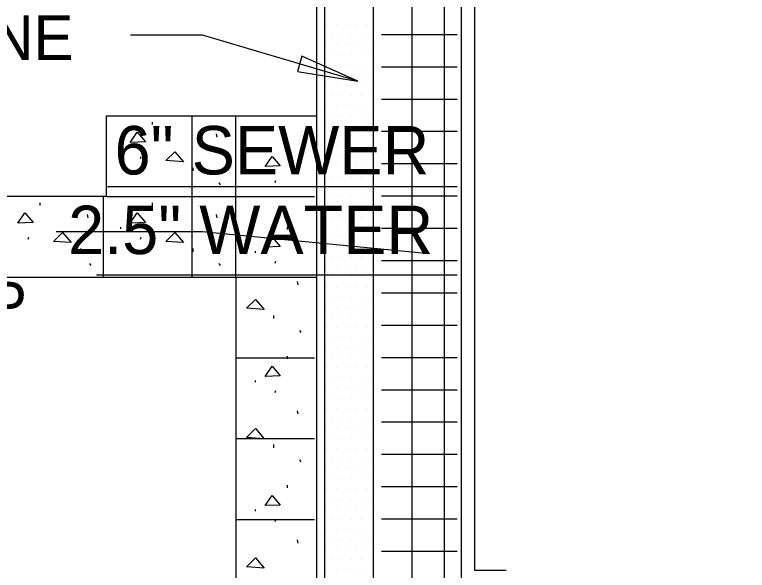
# Model space of a CAD drawing. Extents: x 6712138 to 6712574, y 1869536 to 1870160.
# Drawn here: x 6712232.49 to 6712277.85, y 1869768.11 to 1869802.53 of the extents above; entities that cross this region are included whole.
import ezdxf

# ---------------------------------------------------------------- set-up
doc = ezdxf.new("R2010")
doc.units = 0
for name, color, linetype in [('A-ANNO-TEXT', 7, 'Continuous'), ('A-FLOR-OTLN', 7, 'Continuous'), ('A-FLOR-PATT', 7, 'Continuous'), ('A-WALL-FULL-EXT', 7, 'Continuous'), ('L-SITE-PAVE', 7, 'Continuous')]:
    doc.layers.add(name, color=color, linetype=linetype)

msp = doc.modelspace()

# ---------------------------------------------------------------- linework, layer by layer
at = {"layer": 'A-ANNO-TEXT'}
for p, q in [((6712241.186, 1869801.248), (6712239.67, 1869801.248)), ((6712241.186, 1869801.248), (6712239.67, 1869801.248)), ((6712244.128, 1869801.248), (6712241.186, 1869801.248)), ((6712244.128, 1869801.248), (6712241.186, 1869801.248)), ((6712253.734, 1869798.414), (6712244.128, 1869801.248)), ((6712253.734, 1869798.414), (6712244.128, 1869801.248)), ((6712250.277, 1869799.948), (6712249.997, 1869799.001)), ((6712250.277, 1869799.948), (6712249.997, 1869799.001)), ((6712250.277, 1869799.948), (6712249.997, 1869799.001)), ((6712250.277, 1869799.948), (6712249.997, 1869799.001)), ((6712253.734, 1869798.414), (6712250.277, 1869799.948)), ((6712253.734, 1869798.414), (6712250.277, 1869799.948)), ((6712253.734, 1869798.414), (6712250.277, 1869799.948)), ((6712253.734, 1869798.414), (6712250.277, 1869799.948)), ((6712249.997, 1869799.001), (6712253.734, 1869798.414)), ((6712249.997, 1869799.001), (6712253.734, 1869798.414)), ((6712249.997, 1869799.001), (6712253.734, 1869798.414)), ((6712249.997, 1869799.001), (6712253.734, 1869798.414)), ((6712238.243, 1869791.874), (6712259.891, 1869791.874)), ((6712241.186, 1869789.085), (6712235.058, 1869789.085)), ((6712241.186, 1869789.085), (6712235.058, 1869789.085)), ((6712244.128, 1869789.085), (6712241.186, 1869789.085)), ((6712244.128, 1869789.085), (6712241.186, 1869789.085)), ((6712257.929, 1869787.742), (6712244.128, 1869789.085)), ((6712257.929, 1869787.742), (6712244.128, 1869789.085)), ((6712237.559, 1869786.417), (6712259.891, 1869786.417))]:
    msp.add_line(p, q, dxfattribs=at)
at = {"layer": 'A-FLOR-OTLN'}
for p, q in [((6712238.183, 1869791.27), (6712238.183, 1869796.27)), ((6712238.183, 1869796.27), (6712251.183, 1869796.27)), ((6712238.183, 1869791.27), (6712188.487, 1869791.27)), ((6712188.487, 1869786.27), (6712246.183, 1869786.27)), ((6712246.183, 1869786.27), (6712246.183, 1869759.106))]:
    msp.add_line(p, q, dxfattribs=at)
for points in [[(6712251.183, 1869839.781), (6712251.183, 1869722.323), (6712419.14, 1869722.323), (6712419.14, 1869718.864), (6712468.641, 1869718.864), (6712468.641, 1869839.781)], [(6712251.683, 1869839.281), (6712251.683, 1869722.823), (6712419.64, 1869722.823), (6712419.64, 1869719.364), (6712468.141, 1869719.364), (6712468.141, 1869839.281)]]:
    msp.add_lwpolyline(points, close=True, dxfattribs=at)
msp.add_lwpolyline([(6712254.683, 1869836.281), (6712254.683, 1869725.823), (6712428.12, 1869725.823)], dxfattribs=at)
at = {"layer": 'A-FLOR-PATT'}
for p, q in [((6712257.11, 1869726.344), (6712257.11, 1869835.76)), ((6712259.11, 1869763.052), (6712259.11, 1869835.76)), ((6712251.774, 1869801.907), (6712251.774, 1869801.907)), ((6712252.399, 1869801.907), (6712252.399, 1869801.907)), ((6712253.024, 1869801.907), (6712253.024, 1869801.907)), ((6712253.649, 1869801.907), (6712253.649, 1869801.907)), ((6712254.274, 1869801.907), (6712254.274, 1869801.907)), ((6712252.087, 1869801.282), (6712252.087, 1869801.282)), ((6712252.712, 1869801.282), (6712252.712, 1869801.282)), ((6712253.337, 1869801.282), (6712253.337, 1869801.282)), ((6712253.962, 1869801.282), (6712253.962, 1869801.282)), ((6712254.587, 1869801.282), (6712254.587, 1869801.282)), ((6712259.891, 1869801.281), (6712255.204, 1869801.281)), ((6712251.774, 1869800.657), (6712251.774, 1869800.657)), ((6712252.399, 1869800.657), (6712252.399, 1869800.657)), ((6712253.024, 1869800.657), (6712253.024, 1869800.657)), ((6712253.649, 1869800.657), (6712253.649, 1869800.657)), ((6712254.274, 1869800.657), (6712254.274, 1869800.657)), ((6712252.087, 1869800.032), (6712252.087, 1869800.032)), ((6712252.712, 1869800.032), (6712252.712, 1869800.032)), ((6712253.337, 1869800.032), (6712253.337, 1869800.032)), ((6712253.962, 1869800.032), (6712253.962, 1869800.032)), ((6712254.587, 1869800.032), (6712254.587, 1869800.032)), ((6712251.774, 1869799.407), (6712251.774, 1869799.407)), ((6712252.399, 1869799.407), (6712252.399, 1869799.407)), ((6712253.024, 1869799.407), (6712253.024, 1869799.407)), ((6712253.649, 1869799.407), (6712253.649, 1869799.407)), ((6712254.274, 1869799.407), (6712254.274, 1869799.407)), ((6712259.891, 1869799.281), (6712255.204, 1869799.281)), ((6712252.087, 1869798.782), (6712252.087, 1869798.782)), ((6712252.712, 1869798.782), (6712252.712, 1869798.782)), ((6712253.337, 1869798.782), (6712253.337, 1869798.782)), ((6712253.962, 1869798.782), (6712253.962, 1869798.782)), ((6712254.587, 1869798.782), (6712254.587, 1869798.782)), ((6712251.774, 1869798.157), (6712251.774, 1869798.157)), ((6712252.399, 1869798.157), (6712252.399, 1869798.157)), ((6712253.024, 1869798.157), (6712253.024, 1869798.157)), ((6712253.649, 1869798.157), (6712253.649, 1869798.157)), ((6712254.274, 1869798.157), (6712254.274, 1869798.157)), ((6712252.087, 1869797.532), (6712252.087, 1869797.532)), ((6712252.712, 1869797.532), (6712252.712, 1869797.532)), ((6712253.337, 1869797.532), (6712253.337, 1869797.532)), ((6712253.962, 1869797.532), (6712253.962, 1869797.532)), ((6712254.587, 1869797.532), (6712254.587, 1869797.532)), ((6712259.891, 1869797.281), (6712255.204, 1869797.281)), ((6712251.774, 1869796.907), (6712251.774, 1869796.907)), ((6712252.399, 1869796.907), (6712252.399, 1869796.907)), ((6712253.024, 1869796.907), (6712253.024, 1869796.907)), ((6712253.649, 1869796.907), (6712253.649, 1869796.907)), ((6712254.274, 1869796.907), (6712254.274, 1869796.907)), ((6712252.087, 1869796.282), (6712252.087, 1869796.282)), ((6712252.712, 1869796.282), (6712252.712, 1869796.282)), ((6712253.337, 1869796.282), (6712253.337, 1869796.282)), ((6712253.962, 1869796.282), (6712253.962, 1869796.282)), ((6712254.587, 1869796.282), (6712254.587, 1869796.282)), ((6712241.033, 1869795.715), (6712241.033, 1869795.875)), ((6712251.774, 1869795.657), (6712251.774, 1869795.657)), ((6712252.399, 1869795.657), (6712252.399, 1869795.657)), ((6712253.024, 1869795.657), (6712253.024, 1869795.657)), ((6712253.649, 1869795.657), (6712253.649, 1869795.657)), ((6712254.274, 1869795.657), (6712254.274, 1869795.657)), ((6712245.037, 1869794.946), (6712244.997, 1869795.146)), ((6712252.087, 1869795.032), (6712252.087, 1869795.032)), ((6712252.712, 1869795.032), (6712252.712, 1869795.032)), ((6712253.337, 1869795.032), (6712253.337, 1869795.032)), ((6712253.962, 1869795.032), (6712253.962, 1869795.032)), ((6712254.587, 1869795.032), (6712254.587, 1869795.032)), ((6712259.891, 1869795.281), (6712255.204, 1869795.281)), ((6712251.774, 1869794.407), (6712251.774, 1869794.407)), ((6712252.399, 1869794.407), (6712252.399, 1869794.407)), ((6712253.024, 1869794.407), (6712253.024, 1869794.407)), ((6712253.649, 1869794.407), (6712253.649, 1869794.407)), ((6712254.274, 1869794.407), (6712254.274, 1869794.407)), ((6712239.065, 1869794.264), (6712239.065, 1869794.374)), ((6712249.375, 1869794.221), (6712249.375, 1869794.381)), ((6712240.283, 1869793.625), (6712240.323, 1869793.745)), ((6712252.087, 1869793.782), (6712252.087, 1869793.782)), ((6712252.712, 1869793.782), (6712252.712, 1869793.782)), ((6712253.337, 1869793.782), (6712253.337, 1869793.782)), ((6712253.962, 1869793.782), (6712253.962, 1869793.782)), ((6712254.587, 1869793.782), (6712254.587, 1869793.782)), ((6712243.545, 1869792.847), (6712243.545, 1869793.047)), ((6712251.774, 1869793.157), (6712251.774, 1869793.157)), ((6712252.399, 1869793.157), (6712252.399, 1869793.157)), ((6712253.024, 1869793.157), (6712253.024, 1869793.157)), ((6712253.649, 1869793.157), (6712253.649, 1869793.157)), ((6712254.274, 1869793.157), (6712254.274, 1869793.157)), ((6712259.891, 1869793.281), (6712255.204, 1869793.281)), ((6712247.407, 1869792.77), (6712247.407, 1869792.88)), ((6712248.625, 1869792.131), (6712248.665, 1869792.251)), ((6712252.087, 1869792.532), (6712252.087, 1869792.532)), ((6712252.712, 1869792.532), (6712252.712, 1869792.532)), ((6712253.337, 1869792.532), (6712253.337, 1869792.532)), ((6712253.962, 1869792.532), (6712253.962, 1869792.532)), ((6712254.587, 1869792.532), (6712254.587, 1869792.532)), ((6712245.237, 1869791.986), (6712245.157, 1869792.106)), ((6712251.774, 1869791.907), (6712251.774, 1869791.907)), ((6712252.399, 1869791.907), (6712252.399, 1869791.907)), ((6712253.024, 1869791.907), (6712253.024, 1869791.907)), ((6712253.649, 1869791.907), (6712253.649, 1869791.907)), ((6712254.274, 1869791.907), (6712254.274, 1869791.907)), ((6712252.087, 1869791.282), (6712252.087, 1869791.282)), ((6712252.712, 1869791.282), (6712252.712, 1869791.282)), ((6712253.337, 1869791.282), (6712253.337, 1869791.282)), ((6712253.962, 1869791.282), (6712253.962, 1869791.282)), ((6712254.587, 1869791.282), (6712254.587, 1869791.282)), ((6712259.891, 1869791.281), (6712255.204, 1869791.281)), ((6712234.075, 1869790.715), (6712234.075, 1869790.875)), ((6712241.033, 1869790.715), (6712241.033, 1869790.875)), ((6712251.774, 1869790.657), (6712251.774, 1869790.657)), ((6712252.399, 1869790.657), (6712252.399, 1869790.657)), ((6712253.024, 1869790.657), (6712253.024, 1869790.657)), ((6712253.649, 1869790.657), (6712253.649, 1869790.657)), ((6712254.274, 1869790.657), (6712254.274, 1869790.657)), ((6712237.037, 1869789.946), (6712236.997, 1869790.146)), ((6712245.037, 1869789.946), (6712244.997, 1869790.146)), ((6712252.087, 1869790.032), (6712252.087, 1869790.032)), ((6712252.712, 1869790.032), (6712252.712, 1869790.032)), ((6712253.337, 1869790.032), (6712253.337, 1869790.032)), ((6712253.962, 1869790.032), (6712253.962, 1869790.032)), ((6712254.587, 1869790.032), (6712254.587, 1869790.032)), ((6712239.065, 1869789.264), (6712239.065, 1869789.374)), ((6712249.375, 1869789.221), (6712249.375, 1869789.381)), ((6712251.774, 1869789.407), (6712251.774, 1869789.407)), ((6712252.399, 1869789.407), (6712252.399, 1869789.407)), ((6712253.024, 1869789.407), (6712253.024, 1869789.407)), ((6712253.649, 1869789.407), (6712253.649, 1869789.407)), ((6712254.274, 1869789.407), (6712254.274, 1869789.407)), ((6712259.891, 1869789.281), (6712255.204, 1869789.281)), ((6712233.325, 1869788.625), (6712233.365, 1869788.745)), ((6712240.283, 1869788.625), (6712240.323, 1869788.745)), ((6712252.087, 1869788.782), (6712252.087, 1869788.782)), ((6712252.712, 1869788.782), (6712252.712, 1869788.782)), ((6712253.337, 1869788.782), (6712253.337, 1869788.782)), ((6712253.962, 1869788.782), (6712253.962, 1869788.782)), ((6712254.587, 1869788.782), (6712254.587, 1869788.782)), ((6712251.774, 1869788.157), (6712251.774, 1869788.157)), ((6712252.399, 1869788.157), (6712252.399, 1869788.157)), ((6712253.024, 1869788.157), (6712253.024, 1869788.157)), ((6712253.649, 1869788.157), (6712253.649, 1869788.157)), ((6712254.274, 1869788.157), (6712254.274, 1869788.157)), ((6712236.587, 1869787.847), (6712236.587, 1869788.047)), ((6712243.545, 1869787.847), (6712243.545, 1869788.047)), ((6712247.407, 1869787.77), (6712247.407, 1869787.88)), ((6712248.625, 1869787.131), (6712248.665, 1869787.251)), ((6712252.087, 1869787.532), (6712252.087, 1869787.532)), ((6712252.712, 1869787.532), (6712252.712, 1869787.532)), ((6712253.337, 1869787.532), (6712253.337, 1869787.532)), ((6712253.962, 1869787.532), (6712253.962, 1869787.532)), ((6712254.587, 1869787.532), (6712254.587, 1869787.532)), ((6712259.891, 1869787.281), (6712255.204, 1869787.281)), ((6712237.237, 1869786.986), (6712237.157, 1869787.106)), ((6712245.237, 1869786.986), (6712245.157, 1869787.106)), ((6712251.774, 1869786.907), (6712251.774, 1869786.907)), ((6712252.399, 1869786.907), (6712252.399, 1869786.907)), ((6712253.024, 1869786.907), (6712253.024, 1869786.907)), ((6712253.649, 1869786.907), (6712253.649, 1869786.907)), ((6712254.274, 1869786.907), (6712254.274, 1869786.907)), ((6712252.087, 1869786.282), (6712252.087, 1869786.282)), ((6712252.712, 1869786.282), (6712252.712, 1869786.282)), ((6712253.337, 1869786.282), (6712253.337, 1869786.282)), ((6712253.962, 1869786.282), (6712253.962, 1869786.282)), ((6712254.587, 1869786.282), (6712254.587, 1869786.282)), ((6712250.037, 1869785.8), (6712249.997, 1869786)), ((6712251.774, 1869785.657), (6712251.774, 1869785.657)), ((6712252.399, 1869785.657), (6712252.399, 1869785.657)), ((6712253.024, 1869785.657), (6712253.024, 1869785.657)), ((6712253.649, 1869785.657), (6712253.649, 1869785.657)), ((6712254.274, 1869785.657), (6712254.274, 1869785.657)), ((6712252.087, 1869785.032), (6712252.087, 1869785.032)), ((6712252.712, 1869785.032), (6712252.712, 1869785.032)), ((6712253.337, 1869785.032), (6712253.337, 1869785.032)), ((6712253.962, 1869785.032), (6712253.962, 1869785.032)), ((6712254.587, 1869785.032), (6712254.587, 1869785.032)), ((6712259.891, 1869785.281), (6712255.204, 1869785.281)), ((6712251.774, 1869784.407), (6712251.774, 1869784.407)), ((6712252.399, 1869784.407), (6712252.399, 1869784.407)), ((6712253.024, 1869784.407), (6712253.024, 1869784.407)), ((6712253.649, 1869784.407), (6712253.649, 1869784.407)), ((6712254.274, 1869784.407), (6712254.274, 1869784.407)), ((6712248.545, 1869783.701), (6712248.545, 1869783.901)), ((6712252.087, 1869783.782), (6712252.087, 1869783.782)), ((6712252.712, 1869783.782), (6712252.712, 1869783.782)), ((6712253.337, 1869783.782), (6712253.337, 1869783.782)), ((6712253.962, 1869783.782), (6712253.962, 1869783.782)), ((6712254.587, 1869783.782), (6712254.587, 1869783.782)), ((6712251.774, 1869783.157), (6712251.774, 1869783.157)), ((6712252.399, 1869783.157), (6712252.399, 1869783.157)), ((6712253.024, 1869783.157), (6712253.024, 1869783.157)), ((6712253.649, 1869783.157), (6712253.649, 1869783.157)), ((6712254.274, 1869783.157), (6712254.274, 1869783.157)), ((6712259.891, 1869783.281), (6712255.204, 1869783.281)), ((6712250.237, 1869782.84), (6712250.157, 1869782.96)), ((6712252.087, 1869782.532), (6712252.087, 1869782.532)), ((6712252.712, 1869782.532), (6712252.712, 1869782.532)), ((6712253.337, 1869782.532), (6712253.337, 1869782.532)), ((6712253.962, 1869782.532), (6712253.962, 1869782.532)), ((6712254.587, 1869782.532), (6712254.587, 1869782.532)), ((6712251.774, 1869781.907), (6712251.774, 1869781.907)), ((6712252.399, 1869781.907), (6712252.399, 1869781.907)), ((6712253.024, 1869781.907), (6712253.024, 1869781.907)), ((6712253.649, 1869781.907), (6712253.649, 1869781.907)), ((6712254.274, 1869781.907), (6712254.274, 1869781.907)), ((6712249.375, 1869781.221), (6712249.375, 1869781.381)), ((6712252.087, 1869781.282), (6712252.087, 1869781.282)), ((6712252.712, 1869781.282), (6712252.712, 1869781.282)), ((6712253.337, 1869781.282), (6712253.337, 1869781.282)), ((6712253.962, 1869781.282), (6712253.962, 1869781.282)), ((6712254.587, 1869781.282), (6712254.587, 1869781.282)), ((6712259.891, 1869781.281), (6712255.204, 1869781.281)), ((6712251.774, 1869780.657), (6712251.774, 1869780.657)), ((6712252.399, 1869780.657), (6712252.399, 1869780.657)), ((6712253.024, 1869780.657), (6712253.024, 1869780.657)), ((6712253.649, 1869780.657), (6712253.649, 1869780.657)), ((6712254.274, 1869780.657), (6712254.274, 1869780.657)), ((6712252.087, 1869780.032), (6712252.087, 1869780.032)), ((6712252.712, 1869780.032), (6712252.712, 1869780.032)), ((6712253.337, 1869780.032), (6712253.337, 1869780.032)), ((6712253.962, 1869780.032), (6712253.962, 1869780.032)), ((6712254.587, 1869780.032), (6712254.587, 1869780.032)), ((6712247.407, 1869779.77), (6712247.407, 1869779.88)), ((6712248.625, 1869779.131), (6712248.665, 1869779.251)), ((6712251.774, 1869779.407), (6712251.774, 1869779.407)), ((6712252.399, 1869779.407), (6712252.399, 1869779.407)), ((6712253.024, 1869779.407), (6712253.024, 1869779.407)), ((6712253.649, 1869779.407), (6712253.649, 1869779.407)), ((6712254.274, 1869779.407), (6712254.274, 1869779.407)), ((6712259.891, 1869779.281), (6712255.204, 1869779.281)), ((6712252.087, 1869778.782), (6712252.087, 1869778.782)), ((6712252.712, 1869778.782), (6712252.712, 1869778.782)), ((6712253.337, 1869778.782), (6712253.337, 1869778.782)), ((6712253.962, 1869778.782), (6712253.962, 1869778.782)), ((6712254.587, 1869778.782), (6712254.587, 1869778.782)), ((6712251.774, 1869778.157), (6712251.774, 1869778.157)), ((6712252.399, 1869778.157), (6712252.399, 1869778.157)), ((6712253.024, 1869778.157), (6712253.024, 1869778.157)), ((6712253.649, 1869778.157), (6712253.649, 1869778.157)), ((6712254.274, 1869778.157), (6712254.274, 1869778.157)), ((6712250.037, 1869777.8), (6712249.997, 1869778)), ((6712252.087, 1869777.532), (6712252.087, 1869777.532)), ((6712252.712, 1869777.532), (6712252.712, 1869777.532)), ((6712253.337, 1869777.532), (6712253.337, 1869777.532)), ((6712253.962, 1869777.532), (6712253.962, 1869777.532)), ((6712254.587, 1869777.532), (6712254.587, 1869777.532)), ((6712259.891, 1869777.281), (6712255.204, 1869777.281)), ((6712251.774, 1869776.907), (6712251.774, 1869776.907)), ((6712252.399, 1869776.907), (6712252.399, 1869776.907)), ((6712253.024, 1869776.907), (6712253.024, 1869776.907)), ((6712253.649, 1869776.907), (6712253.649, 1869776.907)), ((6712254.274, 1869776.907), (6712254.274, 1869776.907)), ((6712252.087, 1869776.282), (6712252.087, 1869776.282)), ((6712252.712, 1869776.282), (6712252.712, 1869776.282)), ((6712253.337, 1869776.282), (6712253.337, 1869776.282)), ((6712253.962, 1869776.282), (6712253.962, 1869776.282)), ((6712254.587, 1869776.282), (6712254.587, 1869776.282)), ((6712248.545, 1869775.701), (6712248.545, 1869775.901)), ((6712251.774, 1869775.657), (6712251.774, 1869775.657)), ((6712252.399, 1869775.657), (6712252.399, 1869775.657)), ((6712253.024, 1869775.657), (6712253.024, 1869775.657)), ((6712253.649, 1869775.657), (6712253.649, 1869775.657)), ((6712254.274, 1869775.657), (6712254.274, 1869775.657)), ((6712250.237, 1869774.84), (6712250.157, 1869774.96)), ((6712252.087, 1869775.032), (6712252.087, 1869775.032)), ((6712252.712, 1869775.032), (6712252.712, 1869775.032)), ((6712253.337, 1869775.032), (6712253.337, 1869775.032)), ((6712253.962, 1869775.032), (6712253.962, 1869775.032)), ((6712254.587, 1869775.032), (6712254.587, 1869775.032)), ((6712259.891, 1869775.281), (6712255.204, 1869775.281)), ((6712251.774, 1869774.407), (6712251.774, 1869774.407)), ((6712252.399, 1869774.407), (6712252.399, 1869774.407)), ((6712253.024, 1869774.407), (6712253.024, 1869774.407)), ((6712253.649, 1869774.407), (6712253.649, 1869774.407)), ((6712254.274, 1869774.407), (6712254.274, 1869774.407)), ((6712252.087, 1869773.782), (6712252.087, 1869773.782)), ((6712252.712, 1869773.782), (6712252.712, 1869773.782)), ((6712253.337, 1869773.782), (6712253.337, 1869773.782)), ((6712253.962, 1869773.782), (6712253.962, 1869773.782)), ((6712254.587, 1869773.782), (6712254.587, 1869773.782)), ((6712249.375, 1869773.221), (6712249.375, 1869773.381)), ((6712251.774, 1869773.157), (6712251.774, 1869773.157)), ((6712252.399, 1869773.157), (6712252.399, 1869773.157)), ((6712253.024, 1869773.157), (6712253.024, 1869773.157)), ((6712253.649, 1869773.157), (6712253.649, 1869773.157)), ((6712254.274, 1869773.157), (6712254.274, 1869773.157)), ((6712259.891, 1869773.281), (6712255.204, 1869773.281)), ((6712252.087, 1869772.532), (6712252.087, 1869772.532)), ((6712252.712, 1869772.532), (6712252.712, 1869772.532)), ((6712253.337, 1869772.532), (6712253.337, 1869772.532)), ((6712253.962, 1869772.532), (6712253.962, 1869772.532)), ((6712254.587, 1869772.532), (6712254.587, 1869772.532)), ((6712247.407, 1869771.77), (6712247.407, 1869771.88)), ((6712251.774, 1869771.907), (6712251.774, 1869771.907)), ((6712252.399, 1869771.907), (6712252.399, 1869771.907)), ((6712253.024, 1869771.907), (6712253.024, 1869771.907)), ((6712253.649, 1869771.907), (6712253.649, 1869771.907)), ((6712254.274, 1869771.907), (6712254.274, 1869771.907)), ((6712252.087, 1869771.282), (6712252.087, 1869771.282)), ((6712252.712, 1869771.282), (6712252.712, 1869771.282)), ((6712253.337, 1869771.282), (6712253.337, 1869771.282)), ((6712253.962, 1869771.282), (6712253.962, 1869771.282)), ((6712254.587, 1869771.282), (6712254.587, 1869771.282)), ((6712259.891, 1869771.281), (6712255.204, 1869771.281)), ((6712248.625, 1869771.131), (6712248.665, 1869771.251)), ((6712251.774, 1869770.657), (6712251.774, 1869770.657)), ((6712252.399, 1869770.657), (6712252.399, 1869770.657)), ((6712253.024, 1869770.657), (6712253.024, 1869770.657)), ((6712253.649, 1869770.657), (6712253.649, 1869770.657)), ((6712254.274, 1869770.657), (6712254.274, 1869770.657)), ((6712250.037, 1869769.8), (6712249.997, 1869770)), ((6712252.087, 1869770.032), (6712252.087, 1869770.032)), ((6712252.712, 1869770.032), (6712252.712, 1869770.032)), ((6712253.337, 1869770.032), (6712253.337, 1869770.032)), ((6712253.962, 1869770.032), (6712253.962, 1869770.032)), ((6712254.587, 1869770.032), (6712254.587, 1869770.032)), ((6712251.774, 1869769.407), (6712251.774, 1869769.407)), ((6712252.399, 1869769.407), (6712252.399, 1869769.407)), ((6712253.024, 1869769.407), (6712253.024, 1869769.407)), ((6712253.649, 1869769.407), (6712253.649, 1869769.407)), ((6712254.274, 1869769.407), (6712254.274, 1869769.407)), ((6712259.891, 1869769.281), (6712255.204, 1869769.281)), ((6712252.087, 1869768.782), (6712252.087, 1869768.782)), ((6712252.712, 1869768.782), (6712252.712, 1869768.782)), ((6712253.337, 1869768.782), (6712253.337, 1869768.782)), ((6712253.962, 1869768.782), (6712253.962, 1869768.782)), ((6712254.587, 1869768.782), (6712254.587, 1869768.782)), ((6712251.774, 1869768.157), (6712251.774, 1869768.157)), ((6712252.399, 1869768.157), (6712252.399, 1869768.157)), ((6712253.024, 1869768.157), (6712253.024, 1869768.157)), ((6712253.649, 1869768.157), (6712253.649, 1869768.157)), ((6712254.274, 1869768.157), (6712254.274, 1869768.157))]:
    msp.add_line(p, q, dxfattribs=at)
for points in [[(6712239.655, 1869794.614), (6712240.085, 1869795.244), (6712240.595, 1869794.654)], [(6712241.847, 1869793.486), (6712242.407, 1869794.036), (6712242.947, 1869793.406)], [(6712247.997, 1869793.12), (6712248.427, 1869793.75), (6712248.937, 1869793.16)], [(6712232.697, 1869789.614), (6712233.127, 1869790.244), (6712233.637, 1869789.654)], [(6712239.655, 1869789.614), (6712240.085, 1869790.244), (6712240.595, 1869789.654)], [(6712234.889, 1869788.486), (6712235.449, 1869789.036), (6712235.989, 1869788.406)], [(6712241.847, 1869788.486), (6712242.407, 1869789.036), (6712242.947, 1869788.406)], [(6712247.997, 1869788.12), (6712248.427, 1869788.75), (6712248.937, 1869788.16)], [(6712246.847, 1869784.34), (6712247.407, 1869784.89), (6712247.947, 1869784.26)], [(6712247.997, 1869780.12), (6712248.427, 1869780.75), (6712248.937, 1869780.16)], [(6712246.847, 1869776.34), (6712247.407, 1869776.89), (6712247.947, 1869776.26)], [(6712247.997, 1869772.12), (6712248.427, 1869772.75), (6712248.937, 1869772.16)], [(6712246.847, 1869768.34), (6712247.407, 1869768.89), (6712247.947, 1869768.26)]]:
    msp.add_lwpolyline(points, close=True, dxfattribs=at)
at = {"layer": 'A-WALL-FULL-EXT'}
for p, q in [((6712260.131, 1869807.26), (6712260.131, 1869767.271)), ((6712260.974, 1869768.114), (6712260.974, 1869805.302)), ((6712262.912, 1869768.114), (6712260.974, 1869768.114))]:
    msp.add_line(p, q, dxfattribs=at)
at = {"layer": 'L-SITE-PAVE'}
for p, q in [((6712243.491, 1869786.27), (6712243.491, 1869796.27)), ((6712246.183, 1869786.27), (6712246.183, 1869796.27)), ((6712237.991, 1869786.27), (6712237.991, 1869791.27)), ((6712238.183, 1869791.27), (6712251.046, 1869791.27)), ((6712246.183, 1869786.27), (6712251.183, 1869786.27)), ((6712246.183, 1869781.27), (6712251.046, 1869781.27)), ((6712246.183, 1869776.27), (6712251.046, 1869776.27)), ((6712246.183, 1869771.27), (6712251.046, 1869771.27))]:
    msp.add_line(p, q, dxfattribs=at)

# ---------------------------------------------------------------- texts
at = {"layer": 'A-ANNO-TEXT'}
for s, height, p in [('DG CRUNCH ZONE', 2.76619, (6712202.227, 1869799.712)), ('DG CRUNCH ZONE', 2.76619, (6712202.227, 1869799.712)), ('6" SEWER', 3, (6712238.683, 1869792.63)), ('2.5" WATER', 3, (6712235.807, 1869787.697)), ('MOAT WALL, TYP', 2.76619, (6712202.227, 1869783.222)), ('MOAT WALL, TYP', 2.76619, (6712202.227, 1869783.222))]:
    msp.add_text(s, height=height, dxfattribs=at).set_placement(p)

doc.saveas('drawing.dxf')
